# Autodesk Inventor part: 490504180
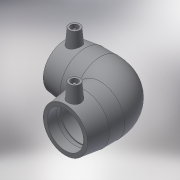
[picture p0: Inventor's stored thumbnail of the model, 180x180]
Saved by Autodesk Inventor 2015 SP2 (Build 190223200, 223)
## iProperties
Created: 2017-06
Part Number: 490504180
Material: Generic
Description: PLASSON 90° ELBOW 180
Document SubType Name: Modeling
Designer: KIM
Mass: 55.0731 g
Surface Area: 148.067 cm^2
Volume: 55.0731 cm^3
Density: 1 g/cm^3
Appearance: Default
Author: KIM
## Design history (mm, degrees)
derived "490504.ipt"
feature "Solid1::490504.ipt"
tag "TaggingFeature1"
body "Solid1"
other parameters: "d2" = 244, "d4" = 103, "d5" = 219.6, "d8" = 168 deg, "d10" = 42, "d11" = 14, "d14" = 17.6296, "d19" = 3.52592, "d20" = 168 deg, "d22" = 224.48, "d23" = 244, "d24" = 217.7456, "d29" = 115, "d30" = 15, "d31" = 144.2, "d34" = 5 deg, "d35" = 15, "d39" = 5 deg, "d41" = 4, "d42" = 14, "d43" = 0, "d45" = 4, "d46" = 14, "d47" = 0, "d50" = 153, "d51" = 42, "d52" = 105, "d54" = 90 deg, "d67" = 45 deg, "d71" = 90 deg, "d75" = 12.2, "d82" = 45 deg, "d83" = 105, "d84" = 219.6, "d86" = 109.8, "d87" = 90 deg, "d90" = 105, "d91" = 0, "d92" = 105, "d93" = 0, "d94" = 90 deg, "d95" = 112.24, "d98" = 412, "d101" = 3, "d102" = 0, "d103" = 3, "d104" = 0, "d105" = 30.45, "d106" = 7.6125, "d107" = 412, "d110" = 57.75, "L_" = 412, "L_1" = 105, "D_" = 244, "A_" = 115, "d_2" = 12
